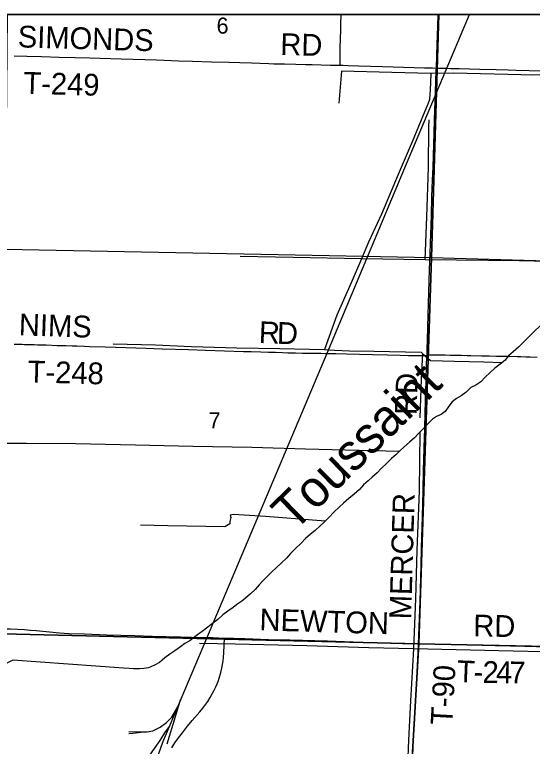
# Model space of a CAD drawing. Extents: x -59 to 43, y 0 to 22.
# Drawn here: x 25.228 to 26.579, y 18.99 to 20.9 of the extents above; entities that cross this region are included whole.
import ezdxf

# ---------------------------------------------------------------- set-up
doc = ezdxf.new("R2010")
doc.units = 0
for name, color, linetype in [('Default', 7, 'Continuous'), ('GM_X_City_Street', 7, 'Continuous'), ('GM_X_Interchange_Ramps', 7, 'Continuous'), ('GM_X_Major_River', 7, 'Continuous'), ('GM_X_Major_River_Text', 7, 'Continuous'), ('GM_X_Minor_River', 7, 'Continuous'), ('GM_X_Rail_Line', 7, 'Continuous'), ('GM_X_Section', 7, 'Continuous'), ('GM_X_Section_Text', 7, 'Continuous'), ('GM_X_Township_Road', 7, 'Continuous'), ('GM_X_Township_Road_Text', 7, 'Continuous'), ('SH_Data', 7, 'Continuous')]:
    doc.layers.add(name, color=color, linetype=linetype)

msp = doc.modelspace()

# ---------------------------------------------------------------- linework, layer by layer
at = {"layer": 'Default'}
for points in [[(26.3353, 20.9), (25.2082, 20.9), (25.2037, 20.3168), (25.2029, 20.288), (26.3156, 20.2658)], [(27.313, 20.9), (26.3353, 20.9), (26.3156, 20.2658), (27.3102, 20.2373)]]:
    msp.add_lwpolyline(points, close=True, dxfattribs=at)
at = {"layer": 'GM_X_City_Street'}
msp.add_lwpolyline([(25.6379, 18.9866), (25.6465, 18.9997), (25.6554, 19.0125), (25.6659, 19.0258), (25.6792, 19.0432), (25.6912, 19.0574), (25.7114, 19.0807), (25.7192, 19.0903), (25.7267, 19.1001), (25.7319, 19.1078), (25.7384, 19.1182), (25.7446, 19.1289), (25.7489, 19.1371), (25.7529, 19.1454), (25.7564, 19.1539), (25.7597, 19.1626), (25.7636, 19.1743), (25.7663, 19.1831), (25.7691, 19.1948), (25.7708, 19.204), (25.7722, 19.2132), (25.7732, 19.2225), (25.7742, 19.2349), (25.7757, 19.273)], dxfattribs=at)
at = {"layer": 'GM_X_Interchange_Ramps'}
msp.add_lwpolyline([(29.3371, 20.9), (25.208, 20.9)], dxfattribs=at)
at = {"layer": 'GM_X_Major_River'}
for points in [[(26.9524, 20.3927), (26.9192, 20.3622), (26.8985, 20.3445), (26.8771, 20.3265), (26.8432, 20.2956), (26.8135, 20.2703), (26.7927, 20.2532), (26.7619, 20.231), (26.7073, 20.1865), (26.6795, 20.1619), (26.6537, 20.1381), (26.6193, 20.1057), (26.5869, 20.0758), (26.5612, 20.0505), (26.543, 20.0319)], [(26.543, 20.0319), (26.5289, 20.0203), (26.5166, 20.0099), (26.5076, 19.9975), (26.4949, 19.9879), (26.4814, 19.9771), (26.4694, 19.9659), (26.4559, 19.954), (26.4447, 19.9417), (26.4316, 19.9332), (26.419, 19.9266), (26.4063, 19.9147), (26.3932, 19.9054), (26.3809, 19.898), (26.3697, 19.8899), (26.3612, 19.8783), (26.3519, 19.8643), (26.3414, 19.8566), (26.3292, 19.8515), (26.319, 19.8442), (26.3053, 19.8314), (26.2944, 19.8191), (26.282, 19.8071), (26.2712, 19.7956), (26.2583, 19.7843), (26.2441, 19.7714), (26.2344, 19.7626), (26.2237, 19.7524), (26.2117, 19.7412), (26.1986, 19.7285), (26.1855, 19.7166), (26.1739, 19.7043), (26.1611, 19.6931), (26.1507, 19.6837), (26.1387, 19.6726), (26.1279, 19.661), (26.1144, 19.6484), (26.1001, 19.6369), (26.0866, 19.6249), (26.0758, 19.6153), (26.0611, 19.6011), (26.0483, 19.5873), (26.0356, 19.5753), (26.0256, 19.566), (26.0124, 19.5537), (26.0001, 19.5441), (25.987, 19.5325), (25.9754, 19.5202), (25.9611, 19.5064), (25.9483, 19.4934), (25.9378, 19.4814), (25.9243, 19.4695), (25.9108, 19.4561), (25.8992, 19.446), (25.8837, 19.4305), (25.8746, 19.4214), (25.8663, 19.412), (25.8555, 19.4001), (25.8435, 19.3881), (25.8307, 19.377), (25.8207, 19.3692), (25.808, 19.3603), (25.7984, 19.3525), (25.7842, 19.3433), (25.7715, 19.3332), (25.7584, 19.3217), (25.7453, 19.3117), (25.7318, 19.3013), (25.7176, 19.2902), (25.7055, 19.2817), (25.6952, 19.2735), (25.6856, 19.266), (25.6726, 19.2587), (25.6606, 19.2498), (25.646, 19.2398), (25.633, 19.2313), (25.6203, 19.2213), (25.6064, 19.2094), (25.5926, 19.202), (25.5777, 19.1955), (25.5651, 19.1934), (25.5543, 19.1925), (25.5383, 19.1928), (25.5265, 19.1936), (25.5124, 19.1944)], [(25.5124, 19.1944), (25.2233, 19.215), (25.1739, 19.1909), (24.9738, 19.2), (24.7971, 19.2063), (24.7069, 19.2091), (24.6992, 19.2036), (24.6938, 19.2003), (24.6806, 19.2016), (24.4447, 19.2065)]]:
    msp.add_lwpolyline(points, dxfattribs=at)
at = {"layer": 'GM_X_Minor_River'}
for points in [[(26.314, 20.7465), (26.3127, 20.7028), (26.3118, 20.693), (26.3104, 20.6782), (26.306, 20.6665), (26.2988, 20.6484), (26.2658, 20.568), (26.2289, 20.4832), (26.1852, 20.3795), (26.1515, 20.306), (26.1333, 20.263), (26.1059, 20.2), (26.069, 20.1156), (26.0366, 20.0257)], [(26.5491, 20.7425), (26.3739, 20.7469), (26.314, 20.7465), (26.2123, 20.7492), (26.0811, 20.7524), (26.0739, 20.6693)], [(27.6392, 20.7146), (27.523, 20.7149), (27.3955, 20.7133), (27.3006, 20.713), (27.1481, 20.7185), (27.0082, 20.7225), (26.8966, 20.7249), (26.8185, 20.7271), (26.8003, 20.7273), (26.7825, 20.7297), (26.7613, 20.7333), (26.73, 20.7373), (26.6963, 20.7409), (26.6685, 20.7406), (26.6446, 20.7401), (26.6105, 20.7426), (26.5764, 20.7424), (26.5491, 20.7425)], [(26.2998, 20.2599), (26.3038, 20.3727), (26.3078, 20.5011), (26.3087, 20.6071), (26.3098, 20.6253)], [(26.5445, 20.2576), (26.2998, 20.2599), (26.1333, 20.263), (25.955, 20.266), (25.817, 20.2686)], [(26.7908, 20.2519), (26.6233, 20.2559), (26.5445, 20.2576)], [(25.4852, 20.0406), (25.5956, 20.0378), (25.6892, 20.0342), (25.8075, 20.0308), (25.9198, 20.0283), (25.9979, 20.0265), (26.0366, 20.0257), (26.0624, 20.0245), (26.1018, 20.023), (26.1651, 20.0218), (26.2891, 20.0195), (26.2928, 20.0156), (26.3134, 19.9977), (26.3763, 19.9958), (26.4525, 19.994), (26.5008, 19.9924)], [(26.2928, 20.0156), (26.2889, 19.9488), (26.2851, 19.8474)], [(26.2319, 19.7602), (25.9873, 19.7663), (25.847, 19.7701), (25.693, 19.7733), (25.5436, 19.7765), (25.3866, 19.7795), (25.2587, 19.7811), (25.1593, 19.7807), (25.1221, 19.7791), (25.1181, 19.6872), (24.9904, 19.6945), (24.8483, 19.7025), (24.8544, 19.7853), (24.8593, 19.8255)], [(26.2851, 19.8101), (26.2841, 19.657), (26.2774, 19.5024), (26.2738, 19.3755), (26.2687, 19.2448), (26.2612, 19.1089), (26.2558, 19.0064), (26.253, 18.9407), (26.2464, 18.8321), (26.2413, 18.7596), (26.2442, 18.6558), (26.2457, 18.5341), (26.2481, 18.4406), (26.2497, 18.3474), (26.2512, 18.2839)], [(26.0389, 19.5784), (25.8826, 19.5904), (25.7992, 19.5954), (25.7905, 19.594), (25.7919, 19.5875), (25.7894, 19.5769), (25.7893, 19.5708), (25.777, 19.5631), (25.6276, 19.5655), (25.5567, 19.568)], [(26.5288, 19.2385), (26.2687, 19.2448), (26.1527, 19.2474), (25.9908, 19.2527), (25.8034, 19.257), (25.7101, 19.2584)], [(27.2833, 19.2245), (26.9862, 19.23), (26.7559, 19.2339), (26.5288, 19.2385)]]:
    msp.add_lwpolyline(points, dxfattribs=at)
at = {"layer": 'GM_X_Rail_Line'}
msp.add_line((25.5262, 19.029), (25.5639, 19.0283), dxfattribs=at)
for points in [[(25.5673, 18.8657), (25.6145, 19.001), (25.73, 19.273), (26.0434, 20.0167), (26.2508, 20.5102), (26.415, 20.9)], [(25.6259, 18.9973), (25.6475, 19.0678), (25.6613, 19.1113)], [(25.5639, 19.0283), (25.5735, 19.0281), (25.5886, 19.0307), (25.6079, 19.04), (25.6247, 19.0527), (25.6379, 19.0664), (25.6539, 19.0938)], [(25.3746, 18.7955), (25.4315, 18.7941), (25.4701, 18.7942), (25.4921, 18.7998), (25.5079, 18.8076), (25.5217, 18.817), (25.532, 18.8282), (25.5399, 18.8398), (25.5462, 18.8545), (25.5657, 18.9285), (25.5754, 18.9585), (25.5889, 18.979), (25.6075, 19.0055), (25.6201, 19.0254), (25.632, 19.0421)], [(25.5258, 19.0241), (25.5366, 19.0243), (25.5639, 19.0283)]]:
    msp.add_lwpolyline(points, dxfattribs=at)
at = {"layer": 'GM_X_Section'}
for points in [[(26.3156, 20.2658), (26.283, 19.2582), (25.1962, 19.2843), (25.1966, 19.318), (25.2029, 20.288)], [(26.3156, 20.2658), (27.3102, 20.2373), (27.2913, 19.2374), (26.283, 19.2582)], [(25.1962, 19.2843), (26.283, 19.2582), (26.2571, 18.8106), (26.2659, 18.2705), (25.1911, 18.2964), (25.1906, 18.3142)], [(26.283, 19.2582), (27.2913, 19.2374), (27.2918, 18.2449), (26.2659, 18.2705), (26.2571, 18.8106)]]:
    msp.add_lwpolyline(points, close=True, dxfattribs=at)
at = {"layer": 'GM_X_Township_Road'}
msp.add_line((25.7757, 19.273), (25.7902, 19.2727), dxfattribs=at)
for points in [[(26.0774, 20.7679), (26.0773, 20.7713), (26.0779, 20.8137), (26.079, 20.8606), (26.0795, 20.8753), (26.08, 20.9)], [(26.3286, 20.7607), (26.3298, 20.7941), (26.3314, 20.847), (26.3321, 20.8687), (26.333, 20.9)], [(25.2268, 20.7924), (25.2597, 20.7914), (25.2977, 20.7905), (25.3443, 20.7893), (25.3859, 20.7882), (25.4245, 20.7871), (25.5059, 20.7846), (25.5979, 20.7817), (25.6184, 20.781), (25.6557, 20.7798), (25.6923, 20.7786), (25.7421, 20.777), (25.7868, 20.7759), (25.8154, 20.7749), (25.8458, 20.7738), (25.8912, 20.7724), (25.9043, 20.772), (25.9322, 20.7715), (25.9621, 20.7707), (25.9869, 20.7702), (26.0044, 20.7698), (26.028, 20.7691), (26.0528, 20.7684), (26.0715, 20.7681), (26.0774, 20.7679)], [(26.0774, 20.7679), (26.0852, 20.7677), (26.0988, 20.7673), (26.1256, 20.7667), (26.1877, 20.7649), (26.271, 20.7623), (26.2977, 20.7615), (26.3189, 20.7609), (26.3286, 20.7607)], [(26.3043, 20.0112), (26.3043, 20.0268), (26.3053, 20.0517), (26.3072, 20.1169), (26.3091, 20.176), (26.3108, 20.235), (26.3123, 20.2754), (26.313, 20.3034), (26.3157, 20.3748), (26.3172, 20.4245), (26.3189, 20.468), (26.32, 20.5022), (26.3212, 20.5332), (26.3221, 20.5612), (26.3241, 20.6233), (26.325, 20.6513), (26.3258, 20.673), (26.3261, 20.6855), (26.3266, 20.701), (26.3275, 20.7227), (26.3284, 20.7569), (26.3286, 20.7607)], [(26.3286, 20.7607), (26.3338, 20.7606), (26.3475, 20.7603), (26.3537, 20.7601), (26.3574, 20.76), (26.3654, 20.7597), (26.3748, 20.7594), (26.3878, 20.7592), (26.4425, 20.7579), (26.4848, 20.7566), (26.5165, 20.7558), (26.537, 20.7551), (26.6396, 20.7522)], [(25.2265, 20.0401), (25.2477, 20.0396), (25.2539, 20.0394), (25.2595, 20.0393), (25.2663, 20.0392), (25.2719, 20.0391), (25.2787, 20.0389), (25.2887, 20.0386), (25.2999, 20.0383), (25.3104, 20.0379), (25.339, 20.0369), (25.3614, 20.0361), (25.3781, 20.0355), (25.39, 20.0352), (25.4105, 20.0346), (25.4235, 20.0341), (25.4645, 20.0327), (25.5714, 20.0294), (25.6131, 20.0281), (25.682, 20.0259), (25.7261, 20.0245), (25.8256, 20.0212), (25.8455, 20.0206), (25.8703, 20.02), (25.8908, 20.0193), (25.9089, 20.0187), (25.9275, 20.0181), (25.9412, 20.0177), (25.9611, 20.0172), (25.9791, 20.0168), (26.0207, 20.0162), (26.0269, 20.0161), (26.0397, 20.0159), (26.0524, 20.0156), (26.0574, 20.0155), (26.0661, 20.0153), (26.094, 20.0149), (26.1618, 20.0132), (26.201, 20.0121), (26.2339, 20.0114), (26.2557, 20.0108), (26.2681, 20.0105), (26.2867, 20.01), (26.2923, 20.0101), (26.2947, 20.0101), (26.2965, 20.0102), (26.2983, 20.0103), (26.3008, 20.0107), (26.3043, 20.0112)], [(26.2983, 19.8174), (26.2984, 19.8254), (26.2992, 19.8564), (26.3001, 19.8937), (26.3018, 19.9434), (26.3033, 19.9869), (26.3041, 20.0055), (26.3043, 20.0112)], [(26.3043, 20.0112), (26.3057, 20.0115), (26.3082, 20.0118), (26.3102, 20.012), (26.3119, 20.0121), (26.3147, 20.0122), (26.3163, 20.0123), (26.3188, 20.0123), (26.3213, 20.0124), (26.3282, 20.0124), (26.34, 20.0121), (26.3518, 20.0118), (26.3643, 20.0116), (26.3792, 20.0113), (26.3947, 20.0109), (26.409, 20.0106), (26.419, 20.0103), (26.4463, 20.0098), (26.4662, 20.0094), (26.4855, 20.009), (26.5004, 20.0088), (26.5141, 20.0085), (26.5203, 20.0083), (26.5402, 20.0076), (26.5495, 20.0074), (26.5625, 20.007), (26.5737, 20.0067), (26.5917, 20.0062)], [(26.2823, 19.2577), (26.2832, 19.2785), (26.285, 19.3251), (26.2866, 19.3686), (26.2893, 19.4618), (26.2901, 19.5084), (26.2921, 19.5892), (26.294, 19.6576), (26.2955, 19.7104), (26.298, 19.7974), (26.2983, 19.8174)], [(25.2, 19.2988), (25.2088, 19.2974), (25.217, 19.2966), (25.2541, 19.2949), (25.2691, 19.2939), (25.2839, 19.293), (25.2925, 19.2921), (25.3014, 19.2911), (25.3447, 19.2865), (25.3571, 19.2855), (25.3695, 19.2849), (25.4099, 19.2837), (25.4689, 19.2817), (25.5417, 19.2793)], [(25.5417, 19.2793), (25.5865, 19.2779), (25.6606, 19.2764), (25.7193, 19.2748), (25.7254, 19.2747)], [(25.7254, 19.2747), (25.744, 19.2741), (25.7757, 19.273)], [(25.7902, 19.2727), (25.8005, 19.2724), (25.8286, 19.2716), (25.8909, 19.2696), (25.9464, 19.2681)], [(25.9464, 19.2681), (26.0444, 19.2654), (26.1557, 19.2616), (26.1757, 19.2609)], [(26.1757, 19.2609), (26.2092, 19.2598), (26.2402, 19.2588), (26.2804, 19.2577), (26.2823, 19.2577)], [(26.2692, 19.01), (26.2705, 19.0363), (26.2721, 19.0611), (26.2733, 19.086), (26.2748, 19.1139), (26.2767, 19.1512), (26.2813, 19.235), (26.2823, 19.2577)], [(26.2823, 19.2577), (26.299, 19.2577), (26.3207, 19.2576), (26.3362, 19.2572), (26.4137, 19.2552), (26.4819, 19.2536), (26.5222, 19.2529), (26.5595, 19.2522), (26.5904, 19.2511), (26.6462, 19.2498), (26.6772, 19.249), (26.7194, 19.2479)], [(26.2587, 18.8103), (26.2597, 18.825), (26.2615, 18.8529), (26.2641, 18.9024), (26.2664, 18.9488), (26.2681, 18.9859), (26.2692, 19.01)]]:
    msp.add_lwpolyline(points, dxfattribs=at)
at = {"layer": 'SH_Data'}
msp.add_lwpolyline([(23.5167, 20.9), (30.3167, 20.9), (30.3167, 14.1), (23.5167, 14.1)], close=True, dxfattribs=at)

# ---------------------------------------------------------------- texts
at = {"layer": 'GM_X_Major_River_Text'}
msp.add_text('Toussaint', height=0.09476, rotation=44.4274, dxfattribs=at).set_placement((25.9567, 19.5481))
at = {"layer": 'GM_X_Section_Text'}
for s, p in [('6', (25.7551, 20.8504)), ('7', (25.7342, 19.8201))]:
    msp.add_text(s, height=0.0419, rotation=0, dxfattribs=at).set_placement(p)
at = {"layer": 'GM_X_Township_Road_Text'}
for s, height, rotation, p in [('SIMONDS', 0.05682, 358.3202, (25.2356, 20.8148)), ('RD', 0.05682, 358.5353, (25.9208, 20.7948)), ('T-249', 0.05682, 358.3324, (25.2503, 20.6939)), ('NIMS', 0.05682, 358.084, (25.2383, 20.0631)), ('R', 0.0568, 357.5677, (25.8644, 20.0431)), ('D', 0.0568, 358.5172, (25.912, 20.0411)), ('T-248', 0.05682, 358.3711, (25.2614, 19.9405)), ('RD', 0.05682, 88.0269, (26.2769, 19.8544)), ('MERCER', 0.05682, 88.3395, (26.2627, 19.3213)), ('NEWTON', 0.05682, 358.2599, (25.8665, 19.2931)), ('RD', 0.05682, 359.0415, (26.4246, 19.2773)), ('T', 0.0568, 357.758, (26.3816, 19.1582)), ('2', 0.0568, 359.1933, (26.4489, 19.156)), ('4', 0.0568, 359.3072, (26.484, 19.1555)), ('7', 0.0568, 359.334, (26.5191, 19.1551)), ('T-90', 0.05682, 86.8258, (26.3702, 19.045)), ('-', 0.0568, 358.9299, (26.4253, 19.1565))]:
    msp.add_text(s, height=height, rotation=rotation, dxfattribs=at).set_placement(p)

doc.saveas('drawing.dxf')
